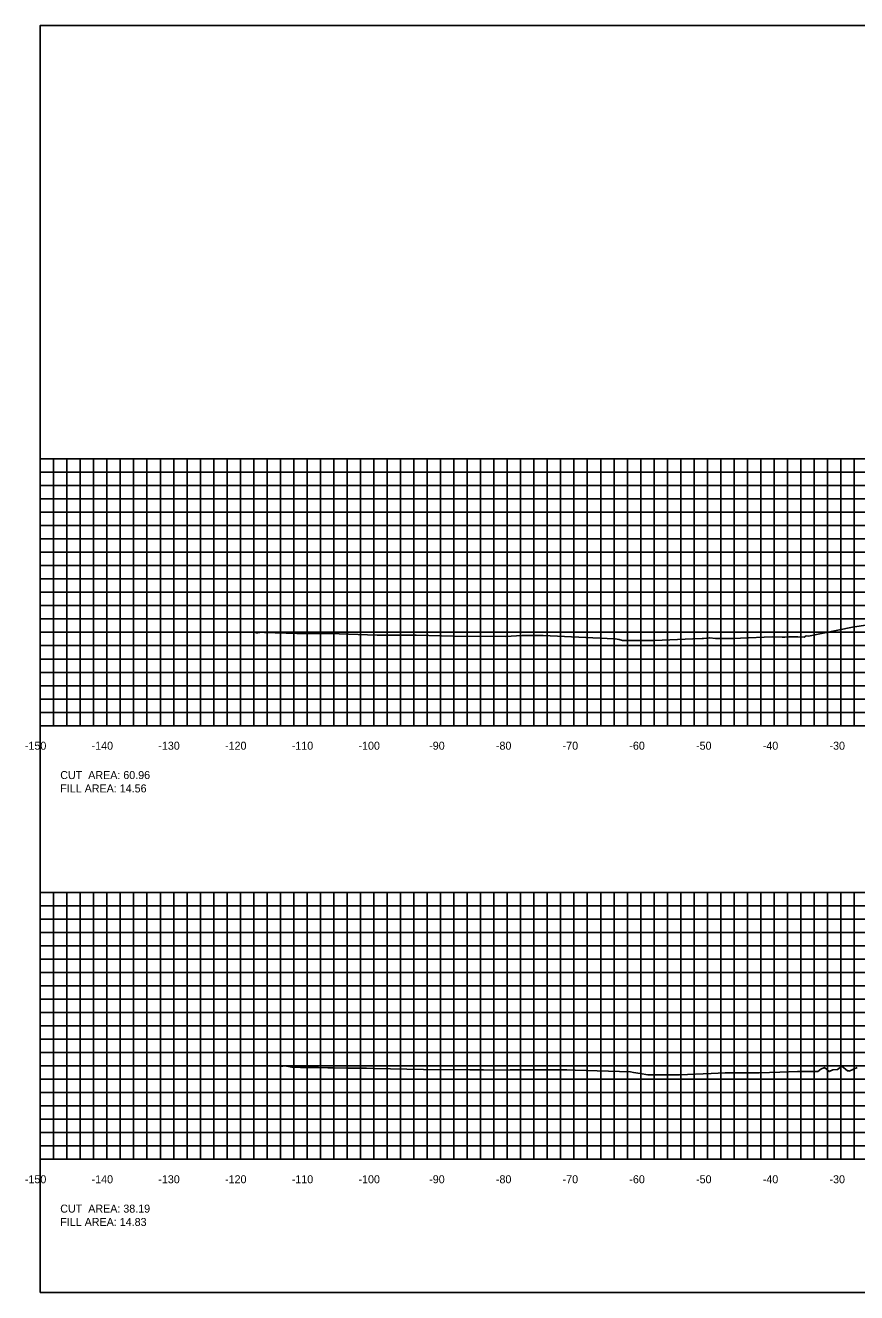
# Model space of a CAD drawing. Extents: x 1797652 to 1804159, y 242516 to 246906.
# Drawn here: x 1802832.3 to 1802956.9, y 242516 to 242706 of the extents above; entities that cross this region are included whole.
import ezdxf

# ---------------------------------------------------------------- set-up
doc = ezdxf.new("R2010")
doc.units = 0
for name, color, linetype in [('10', 7, 'Continuous'), ('60', 7, 'Continuous'), ('Level 62', 7, 'Continuous'), ('M-ROADS', 7, 'Continuous')]:
    doc.layers.add(name, color=color, linetype=linetype)

msp = doc.modelspace()

# ---------------------------------------------------------------- linework, layer by layer
msp.add_lwpolyline([(1802834.49, 242516), (1803134.49, 242516), (1803134.49, 242706), (1802834.49, 242706)], close=True)
at = {"layer": '60'}
for p, q in [((1802834.43, 242641), (1802834.49, 242641)), ((1802834.49, 242601), (1802834.49, 242641)), ((1802834.43, 242631), (1802834.49, 242631)), ((1802834.43, 242621), (1802834.49, 242621)), ((1802834.43, 242611), (1802834.49, 242611)), ((1802834.43, 242601), (1802834.49, 242601)), ((1802834.49, 242601), (1803134.49, 242601)), ((1802834.49, 242600.94), (1802834.49, 242601)), ((1802844.49, 242600.94), (1802844.49, 242601)), ((1802854.49, 242600.94), (1802854.49, 242601)), ((1802864.49, 242600.94), (1802864.49, 242601)), ((1802874.49, 242600.94), (1802874.49, 242601)), ((1802884.49, 242600.94), (1802884.49, 242601)), ((1802894.49, 242600.94), (1802894.49, 242601)), ((1802904.49, 242600.94), (1802904.49, 242601)), ((1802914.49, 242600.94), (1802914.49, 242601)), ((1802924.49, 242600.94), (1802924.49, 242601)), ((1802934.49, 242600.94), (1802934.49, 242601)), ((1802944.49, 242600.94), (1802944.49, 242601)), ((1802954.49, 242600.94), (1802954.49, 242601)), ((1802834.43, 242576), (1802834.49, 242576)), ((1802834.49, 242536), (1802834.49, 242576)), ((1802834.43, 242566), (1802834.49, 242566)), ((1802834.43, 242556), (1802834.49, 242556)), ((1802834.43, 242546), (1802834.49, 242546)), ((1802834.43, 242536), (1802834.49, 242536)), ((1802834.49, 242536), (1803134.49, 242536)), ((1802834.49, 242535.94), (1802834.49, 242536)), ((1802844.49, 242535.94), (1802844.49, 242536)), ((1802854.49, 242535.94), (1802854.49, 242536)), ((1802864.49, 242535.94), (1802864.49, 242536)), ((1802874.49, 242535.94), (1802874.49, 242536)), ((1802884.49, 242535.94), (1802884.49, 242536)), ((1802894.49, 242535.94), (1802894.49, 242536)), ((1802904.49, 242535.94), (1802904.49, 242536)), ((1802914.49, 242535.94), (1802914.49, 242536)), ((1802924.49, 242535.94), (1802924.49, 242536)), ((1802934.49, 242535.94), (1802934.49, 242536)), ((1802944.49, 242535.94), (1802944.49, 242536)), ((1802954.49, 242535.94), (1802954.49, 242536))]:
    msp.add_line(p, q, dxfattribs=at)
at = {"layer": 'Level 62'}
for p, q in [((1802834.49, 242641), (1803134.49, 242641)), ((1802834.49, 242601), (1802834.49, 242641)), ((1802836.49, 242601), (1802836.49, 242641)), ((1802838.49, 242601), (1802838.49, 242641)), ((1802840.49, 242601), (1802840.49, 242641)), ((1802842.49, 242601), (1802842.49, 242641)), ((1802844.49, 242601), (1802844.49, 242641)), ((1802846.49, 242601), (1802846.49, 242641)), ((1802848.49, 242601), (1802848.49, 242641)), ((1802850.49, 242601), (1802850.49, 242641)), ((1802852.49, 242601), (1802852.49, 242641)), ((1802854.49, 242601), (1802854.49, 242641)), ((1802856.49, 242601), (1802856.49, 242641)), ((1802858.49, 242601), (1802858.49, 242641)), ((1802860.49, 242601), (1802860.49, 242641)), ((1802862.49, 242601), (1802862.49, 242641)), ((1802864.49, 242601), (1802864.49, 242641)), ((1802866.49, 242601), (1802866.49, 242641)), ((1802868.49, 242601), (1802868.49, 242641)), ((1802870.49, 242601), (1802870.49, 242641)), ((1802872.49, 242601), (1802872.49, 242641)), ((1802874.49, 242601), (1802874.49, 242641)), ((1802876.49, 242601), (1802876.49, 242641)), ((1802878.49, 242601), (1802878.49, 242641)), ((1802880.49, 242601), (1802880.49, 242641)), ((1802882.49, 242601), (1802882.49, 242641)), ((1802884.49, 242601), (1802884.49, 242641)), ((1802886.49, 242601), (1802886.49, 242641)), ((1802888.49, 242601), (1802888.49, 242641)), ((1802890.49, 242601), (1802890.49, 242641)), ((1802892.49, 242601), (1802892.49, 242641)), ((1802894.49, 242601), (1802894.49, 242641)), ((1802896.49, 242601), (1802896.49, 242641)), ((1802898.49, 242601), (1802898.49, 242641)), ((1802900.49, 242601), (1802900.49, 242641)), ((1802902.49, 242601), (1802902.49, 242641)), ((1802904.49, 242601), (1802904.49, 242641)), ((1802906.49, 242601), (1802906.49, 242641)), ((1802908.49, 242601), (1802908.49, 242641)), ((1802910.49, 242601), (1802910.49, 242641)), ((1802912.49, 242601), (1802912.49, 242641)), ((1802914.49, 242601), (1802914.49, 242641)), ((1802916.49, 242601), (1802916.49, 242641)), ((1802918.49, 242601), (1802918.49, 242641)), ((1802920.49, 242601), (1802920.49, 242641)), ((1802922.49, 242601), (1802922.49, 242641)), ((1802924.49, 242601), (1802924.49, 242641)), ((1802926.49, 242601), (1802926.49, 242641)), ((1802928.49, 242601), (1802928.49, 242641)), ((1802930.49, 242601), (1802930.49, 242641)), ((1802932.49, 242601), (1802932.49, 242641)), ((1802934.49, 242601), (1802934.49, 242641)), ((1802936.49, 242601), (1802936.49, 242641)), ((1802938.49, 242601), (1802938.49, 242641)), ((1802940.49, 242601), (1802940.49, 242641)), ((1802942.49, 242601), (1802942.49, 242641)), ((1802944.49, 242601), (1802944.49, 242641)), ((1802946.49, 242601), (1802946.49, 242641)), ((1802948.49, 242601), (1802948.49, 242641)), ((1802950.49, 242601), (1802950.49, 242641)), ((1802952.49, 242601), (1802952.49, 242641)), ((1802954.49, 242601), (1802954.49, 242641)), ((1802956.49, 242601), (1802956.49, 242641)), ((1802834.49, 242639), (1803134.49, 242639)), ((1802834.49, 242637), (1803134.49, 242637)), ((1802834.49, 242635), (1803134.49, 242635)), ((1802834.49, 242633), (1803134.49, 242633)), ((1802834.49, 242631), (1803134.49, 242631)), ((1802834.49, 242629), (1803134.49, 242629)), ((1802834.49, 242627), (1803134.49, 242627)), ((1802834.49, 242625), (1803134.49, 242625)), ((1802834.49, 242623), (1803134.49, 242623)), ((1802834.49, 242621), (1803134.49, 242621)), ((1802834.49, 242619), (1803134.49, 242619)), ((1802834.49, 242617), (1803134.49, 242617)), ((1802834.49, 242615), (1803134.49, 242615)), ((1802834.49, 242613), (1803134.49, 242613)), ((1802834.49, 242611), (1803134.49, 242611)), ((1802834.49, 242609), (1803134.49, 242609)), ((1802834.49, 242607), (1803134.49, 242607)), ((1802834.49, 242605), (1803134.49, 242605)), ((1802834.49, 242603), (1803134.49, 242603)), ((1802834.49, 242601), (1803134.49, 242601)), ((1802834.49, 242576), (1803134.49, 242576)), ((1802834.49, 242536), (1802834.49, 242576)), ((1802836.49, 242536), (1802836.49, 242576)), ((1802838.49, 242536), (1802838.49, 242576)), ((1802840.49, 242536), (1802840.49, 242576)), ((1802842.49, 242536), (1802842.49, 242576)), ((1802844.49, 242536), (1802844.49, 242576)), ((1802846.49, 242536), (1802846.49, 242576)), ((1802848.49, 242536), (1802848.49, 242576)), ((1802850.49, 242536), (1802850.49, 242576)), ((1802852.49, 242536), (1802852.49, 242576)), ((1802854.49, 242536), (1802854.49, 242576)), ((1802856.49, 242536), (1802856.49, 242576)), ((1802858.49, 242536), (1802858.49, 242576)), ((1802860.49, 242536), (1802860.49, 242576)), ((1802862.49, 242536), (1802862.49, 242576)), ((1802864.49, 242536), (1802864.49, 242576)), ((1802866.49, 242536), (1802866.49, 242576)), ((1802868.49, 242536), (1802868.49, 242576)), ((1802870.49, 242536), (1802870.49, 242576)), ((1802872.49, 242536), (1802872.49, 242576)), ((1802874.49, 242536), (1802874.49, 242576)), ((1802876.49, 242536), (1802876.49, 242576)), ((1802878.49, 242536), (1802878.49, 242576)), ((1802880.49, 242536), (1802880.49, 242576)), ((1802882.49, 242536), (1802882.49, 242576)), ((1802884.49, 242536), (1802884.49, 242576)), ((1802886.49, 242536), (1802886.49, 242576)), ((1802888.49, 242536), (1802888.49, 242576)), ((1802890.49, 242536), (1802890.49, 242576)), ((1802892.49, 242536), (1802892.49, 242576)), ((1802894.49, 242536), (1802894.49, 242576)), ((1802896.49, 242536), (1802896.49, 242576)), ((1802898.49, 242536), (1802898.49, 242576)), ((1802900.49, 242536), (1802900.49, 242576)), ((1802902.49, 242536), (1802902.49, 242576)), ((1802904.49, 242536), (1802904.49, 242576)), ((1802906.49, 242536), (1802906.49, 242576)), ((1802908.49, 242536), (1802908.49, 242576)), ((1802910.49, 242536), (1802910.49, 242576)), ((1802912.49, 242536), (1802912.49, 242576)), ((1802914.49, 242536), (1802914.49, 242576)), ((1802916.49, 242536), (1802916.49, 242576)), ((1802918.49, 242536), (1802918.49, 242576)), ((1802920.49, 242536), (1802920.49, 242576)), ((1802922.49, 242536), (1802922.49, 242576)), ((1802924.49, 242536), (1802924.49, 242576)), ((1802926.49, 242536), (1802926.49, 242576)), ((1802928.49, 242536), (1802928.49, 242576)), ((1802930.49, 242536), (1802930.49, 242576)), ((1802932.49, 242536), (1802932.49, 242576)), ((1802934.49, 242536), (1802934.49, 242576)), ((1802936.49, 242536), (1802936.49, 242576)), ((1802938.49, 242536), (1802938.49, 242576)), ((1802940.49, 242536), (1802940.49, 242576)), ((1802942.49, 242536), (1802942.49, 242576)), ((1802944.49, 242536), (1802944.49, 242576)), ((1802946.49, 242536), (1802946.49, 242576)), ((1802948.49, 242536), (1802948.49, 242576)), ((1802950.49, 242536), (1802950.49, 242576)), ((1802952.49, 242536), (1802952.49, 242576)), ((1802954.49, 242536), (1802954.49, 242576)), ((1802956.49, 242536), (1802956.49, 242576)), ((1802834.49, 242574), (1803134.49, 242574)), ((1802834.49, 242572), (1803134.49, 242572)), ((1802834.49, 242570), (1803134.49, 242570)), ((1802834.49, 242568), (1803134.49, 242568)), ((1802834.49, 242566), (1803134.49, 242566)), ((1802834.49, 242564), (1803134.49, 242564)), ((1802834.49, 242562), (1803134.49, 242562)), ((1802834.49, 242560), (1803134.49, 242560)), ((1802834.49, 242558), (1803134.49, 242558)), ((1802834.49, 242556), (1803134.49, 242556)), ((1802834.49, 242554), (1803134.49, 242554)), ((1802834.49, 242552), (1803134.49, 242552)), ((1802834.49, 242550), (1803134.49, 242550)), ((1802834.49, 242548), (1803134.49, 242548)), ((1802834.49, 242546), (1803134.49, 242546)), ((1802834.49, 242544), (1803134.49, 242544)), ((1802834.49, 242542), (1803134.49, 242542)), ((1802834.49, 242540), (1803134.49, 242540)), ((1802834.49, 242538), (1803134.49, 242538)), ((1802834.49, 242536), (1803134.49, 242536))]:
    msp.add_line(p, q, dxfattribs=at)
at = {"layer": 'M-ROADS'}
for points in [[(1802866.81, 242614.86), (1802867.7, 242615.04), (1802868.12, 242614.95), (1802872.97, 242614.84), (1802874.03, 242614.82), (1802875.61, 242614.82), (1802876.68, 242614.82), (1802877.84, 242614.82), (1802884.97, 242614.56), (1802885.08, 242614.56), (1802885.2, 242614.56), (1802887.84, 242614.56), (1802888.88, 242614.56), (1802890.29, 242614.55), (1802890.86, 242614.55), (1802896.53, 242614.42), (1802904.21, 242614.39), (1802906.7, 242614.5), (1802907.67, 242614.51), (1802909.89, 242614.54), (1802919.44, 242614.08), (1802920.66, 242614.03), (1802921.26, 242613.94), (1802921.78, 242613.76), (1802923.3, 242613.75), (1802923.38, 242613.75), (1802923.46, 242613.78), (1802923.55, 242613.75), (1802924.29, 242613.76), (1802924.95, 242613.77), (1802925.65, 242613.76), (1802926.55, 242613.76), (1802932.31, 242614.03), (1802933.7, 242614.09), (1802933.92, 242614.09), (1802934.82, 242614.16), (1802934.87, 242614.16), (1802935.7, 242614.08), (1802936.29, 242614.08), (1802936.64, 242614.08), (1802936.87, 242614.09), (1802938.08, 242614.08), (1802938.28, 242614.08), (1802938.47, 242614.07), (1802938.55, 242614.08), (1802939.46, 242614.11), (1802944.21, 242614.3), (1802945.67, 242614.28), (1802945.81, 242614.28), (1802946.08, 242614.29), (1802946.69, 242614.3), (1802947.38, 242614.31), (1802948.03, 242614.3), (1802948.98, 242614.29), (1802949.27, 242614.45), (1802949.64, 242614.42), (1802956.22, 242615.77), (1802961.46, 242616.56)], [(1802870.55, 242549.89), (1802871.14, 242550.01), (1802872.21, 242549.8), (1802873.52, 242549.76), (1802874.71, 242549.74), (1802876.21, 242549.75), (1802877.62, 242549.73), (1802878.38, 242549.71), (1802880.39, 242549.65), (1802883.41, 242549.64), (1802884.47, 242549.63), (1802891.93, 242549.46), (1802898.89, 242549.42), (1802900.93, 242549.41), (1802902.56, 242549.38), (1802904.95, 242549.39), (1802905.75, 242549.39), (1802906.05, 242549.39), (1802913.43, 242549.39), (1802914.69, 242549.36), (1802922.94, 242549.09), (1802923.42, 242549.02), (1802924.39, 242548.86), (1802925.54, 242548.66), (1802926.58, 242548.65), (1802927.15, 242548.65), (1802927.85, 242548.65), (1802928.34, 242548.66), (1802928.71, 242548.67), (1802928.88, 242548.67), (1802930.32, 242548.65), (1802935.03, 242548.85), (1802937.16, 242548.94), (1802937.47, 242548.95), (1802938.52, 242548.94), (1802939.08, 242548.94), (1802939.19, 242548.94), (1802939.34, 242548.94), (1802940.11, 242548.96), (1802940.64, 242548.95), (1802941.66, 242548.96), (1802942.25, 242548.96), (1802945.32, 242549.07), (1802948.01, 242549.16), (1802948.53, 242549.15), (1802949.61, 242549.14), (1802950.12, 242549.15), (1802950.85, 242549.16), (1802951.04, 242549.16), (1802951.5, 242549.5), (1802952.05, 242549.74), (1802952.72, 242549.14), (1802953.3, 242549.4), (1802953.97, 242549.46), (1802954.62, 242549.97), (1802955.49, 242549.27), (1802955.68, 242549.25), (1802955.76, 242549.21), (1802956.92, 242549.77)]]:
    msp.add_lwpolyline(points, dxfattribs=at)

# ---------------------------------------------------------------- texts
at = {"layer": '10'}
for s, p in [('-150', (1802832.19, 242597.4)), ('-140', (1802842.19, 242597.4)), ('-130', (1802852.19, 242597.4)), ('-120', (1802862.19, 242597.4)), ('-110', (1802872.19, 242597.4)), ('-100', (1802882.19, 242597.4)), ('-90', (1802892.79, 242597.4)), ('-80', (1802902.79, 242597.4)), ('-70', (1802912.79, 242597.4)), ('-60', (1802922.79, 242597.4)), ('-50', (1802932.79, 242597.4)), ('-40', (1802942.79, 242597.4)), ('-30', (1802952.79, 242597.4)), ('CUT  AREA: 60.96', (1802837.49, 242593)), ('FILL AREA: 14.56', (1802837.49, 242591)), ('-150', (1802832.19, 242532.4)), ('-140', (1802842.19, 242532.4)), ('-130', (1802852.19, 242532.4)), ('-120', (1802862.19, 242532.4)), ('-110', (1802872.19, 242532.4)), ('-100', (1802882.19, 242532.4)), ('-90', (1802892.79, 242532.4)), ('-80', (1802902.79, 242532.4)), ('-70', (1802912.79, 242532.4)), ('-60', (1802922.79, 242532.4)), ('-50', (1802932.79, 242532.4)), ('-40', (1802942.79, 242532.4)), ('-30', (1802952.79, 242532.4)), ('CUT  AREA: 38.19', (1802837.49, 242528)), ('FILL AREA: 14.83', (1802837.49, 242526))]:
    msp.add_text(s, height=1.2, dxfattribs=at).set_placement(p)
at = {"layer": '60'}
for p in [(1802834.49, 242601), (1802834.49, 242536)]:
    msp.add_text('-', height=0.0001, dxfattribs=at).set_placement(p)

doc.saveas('drawing.dxf')
